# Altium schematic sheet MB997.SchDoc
size A4; DocumentNumber: 1; Revision: C.1(PCB.SCH); SheetNumber: 1; SheetTotal: 6; PageSetup: Record=PageOptions|CenterHorizontal=True|CenterVertical=True|PrintScale=1.00|XCorrection=1.00|YCorrection=1.00|PrintKind=1|BorderSize=5000000|LeftOffset=0|BottomOffset=0|Orientation=2|PaperLength=1000|PaperWidth=1000|Scale=100|PaperSource=15|PrintQuality=1200|MediaType=1|DitherType=10|PaperKind=A4|PrintScaleMode=1
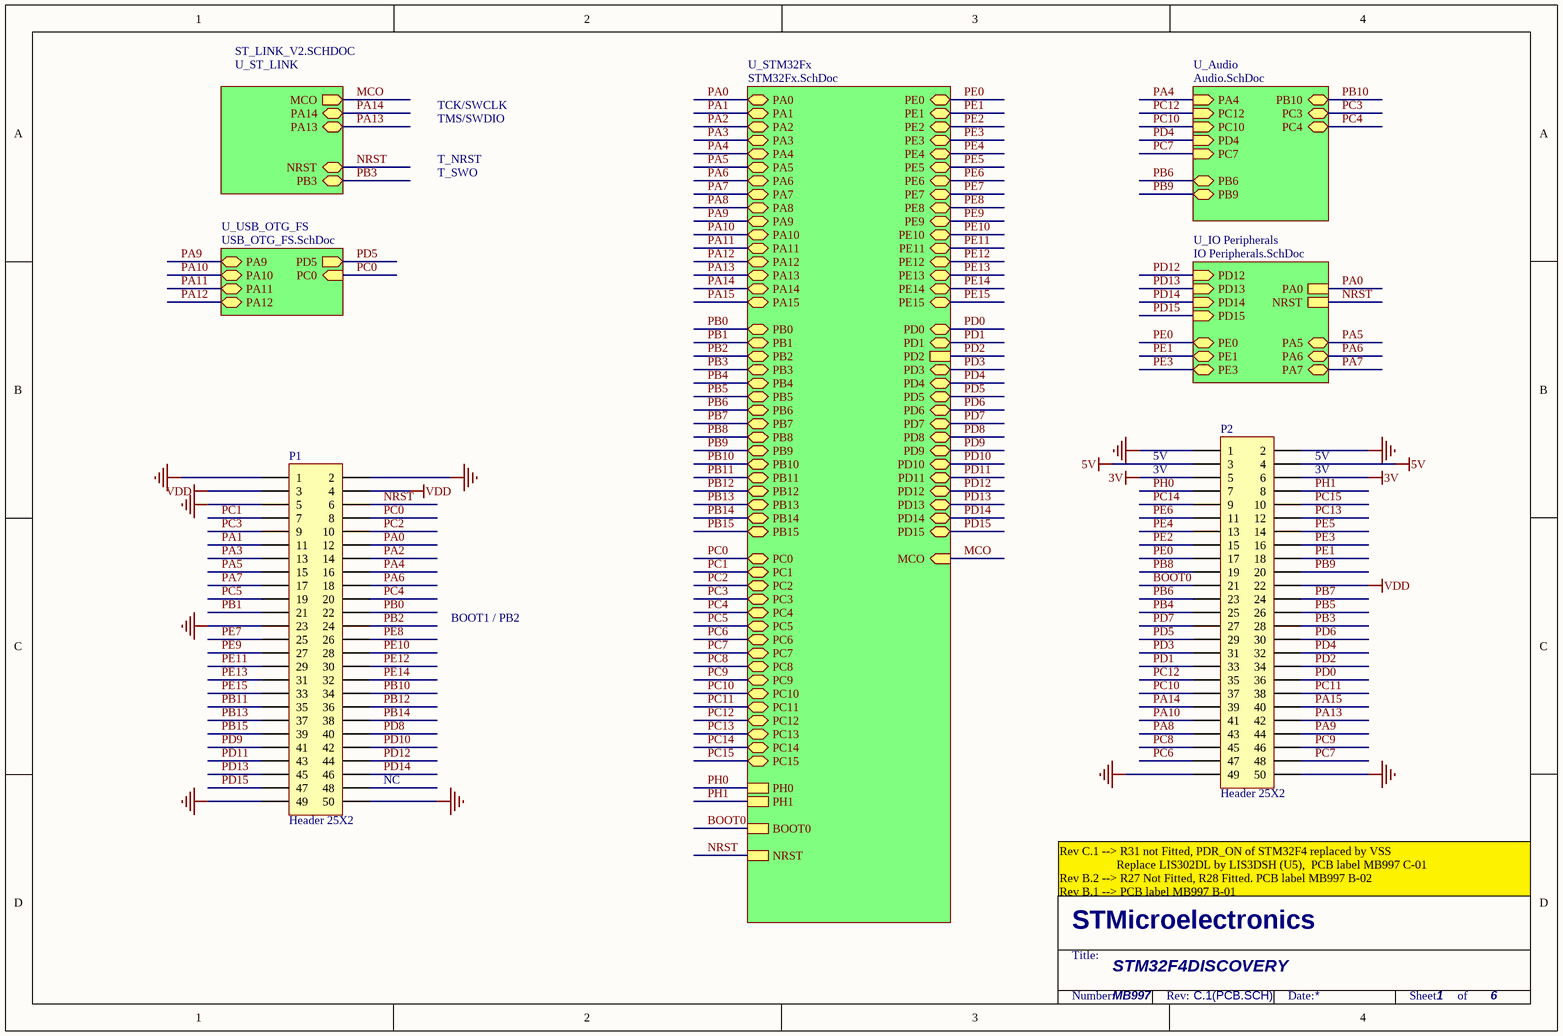
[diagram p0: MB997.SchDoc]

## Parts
P1  Header 25X2  [HDR2X25]
P2  Header 25X2  [HDR2X25]

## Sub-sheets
U_Audio = Audio.SchDoc: PA4 (in), PC12 (in), PC10 (in), PB6 (bidir), PB9 (bidir), PD4 (in), PC7 (in), PC3, PB10, PC4
U_IO Peripherals = IO Peripherals.SchDoc: PA0, NRST, PD12 (in), PE0, PD13 (in), PD14 (in), PD15 (in), PE1, PA5 (bidir), PA7 (bidir), PE3, PA6 (bidir)
U_ST_LINK = ST_LINK_V2.SCHDOC: PA13, PA14, NRST, PB3, MCO (out)
U_STM32Fx = STM32Fx.SchDoc: PA13 (bidir), PA14 (bidir), PA15 (bidir), PA12 (bidir), PA0 (bidir), PA1 (bidir), PA2 (bidir), PA3 (bidir), PA4 (bidir), PA5 (bidir), PA6 (bidir), PA7 (bidir), PA8 (bidir), PA9 (bidir), PA10 (bidir), PA11 (bidir), PB12 (bidir), PB0 (bidir), PB1 (bidir), PB2 (bidir), PB3 (bidir), PB4 (bidir), PB5 (bidir), PB6 (bidir), PB7 (bidir), PB8 (bidir), PB9 (bidir), PB10 (bidir), PB11 (bidir), PB13 (bidir), PB14 (bidir), PB15 (bidir), PC3 (bidir), PC15 (bidir), PC14 (bidir), PC13 (bidir), PC12 (bidir), PC11 (bidir), PC10 (bidir), PC9 (bidir), PC8 (bidir), PC7 (bidir), PC6 (bidir), PC5 (bidir), PC4 (bidir), PC2 (bidir), PC1 (bidir), PC0 (bidir), PD2, BOOT0, PH1, PH0, NRST, MCO (in), PE0, PE1, PE2, PE3, PE4, PE5, PE6, PE7, PE8, PE9, PE10, PE11, PE12, PE13, PE14, PE15, PD0, PD1, PD3, PD4, PD5, PD6, PD7, PD8, PD9, PD10, PD11, PD12, PD13, PD14, PD15
U_USB_OTG_FS = USB_OTG_FS.SchDoc: PD5 (out), PA11 (bidir), PA12 (bidir), PC0 (in), PA10 (bidir), PA9 (bidir)

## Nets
3V: P2.5 P2.6
5V: P2.3 P2.4
GND: P1.1 P1.2 P1.5 P1.23 P1.49 P1.50 P2.1 P2.2 P2.49 P2.50
VDD: P1.3 P1.4 P2.22
BOOT0: P2.21 ; sheet U_STM32Fx/BOOT0
MCO: sheet U_ST_LINK/MCO, sheet U_STM32Fx/MCO
NRST: P1.6 ; sheet U_ST_LINK/NRST, sheet U_IO Peripherals/NRST, sheet U_STM32Fx/NRST
PA0: P1.12 ; sheet U_IO Peripherals/PA0, sheet U_STM32Fx/PA0
PA1: P1.11 ; sheet U_STM32Fx/PA1
PA2: P1.14 ; sheet U_STM32Fx/PA2
PA3: P1.13 ; sheet U_STM32Fx/PA3
PA4: P1.16 ; sheet U_Audio/PA4, sheet U_STM32Fx/PA4
PA5: P1.15 ; sheet U_IO Peripherals/PA5, sheet U_STM32Fx/PA5
PA6: P1.18 ; sheet U_IO Peripherals/PA6, sheet U_STM32Fx/PA6
PA7: P1.17 ; sheet U_IO Peripherals/PA7, sheet U_STM32Fx/PA7
PA8: P2.43 ; sheet U_STM32Fx/PA8
PA9: P2.44 ; sheet U_STM32Fx/PA9, sheet U_USB_OTG_FS/PA9
PA10: P2.41 ; sheet U_STM32Fx/PA10, sheet U_USB_OTG_FS/PA10
PA11: sheet U_STM32Fx/PA11, sheet U_USB_OTG_FS/PA11
PA12: sheet U_STM32Fx/PA12, sheet U_USB_OTG_FS/PA12
PA13: P2.42 ; sheet U_ST_LINK/PA13, sheet U_STM32Fx/PA13
PA14: P2.39 ; sheet U_ST_LINK/PA14, sheet U_STM32Fx/PA14
PA15: P2.40 ; sheet U_STM32Fx/PA15
PB0: P1.22 ; sheet U_STM32Fx/PB0
PB1: P1.21 ; sheet U_STM32Fx/PB1
PB2: P1.24 ; sheet U_STM32Fx/PB2
PB3: P2.28 ; sheet U_ST_LINK/PB3, sheet U_STM32Fx/PB3
PB4: P2.25 ; sheet U_STM32Fx/PB4
PB5: P2.26 ; sheet U_STM32Fx/PB5
PB6: P2.23 ; sheet U_Audio/PB6, sheet U_STM32Fx/PB6
PB7: P2.24 ; sheet U_STM32Fx/PB7
PB8: P2.19 ; sheet U_STM32Fx/PB8
PB9: P2.20 ; sheet U_Audio/PB9, sheet U_STM32Fx/PB9
PB10: P1.34 ; sheet U_Audio/PB10, sheet U_STM32Fx/PB10
PB11: P1.35 ; sheet U_STM32Fx/PB11
PB12: P1.36 ; sheet U_STM32Fx/PB12
PB13: P1.37 ; sheet U_STM32Fx/PB13
PB14: P1.38 ; sheet U_STM32Fx/PB14
PB15: P1.39 ; sheet U_STM32Fx/PB15
PC0: P1.8 ; sheet U_STM32Fx/PC0, sheet U_USB_OTG_FS/PC0
PC1: P1.7 ; sheet U_STM32Fx/PC1
PC2: P1.10 ; sheet U_STM32Fx/PC2
PC3: P1.9 ; sheet U_Audio/PC3, sheet U_STM32Fx/PC3
PC4: P1.20 ; sheet U_Audio/PC4, sheet U_STM32Fx/PC4
PC5: P1.19 ; sheet U_STM32Fx/PC5
PC6: P2.47 ; sheet U_STM32Fx/PC6
PC7: P2.48 ; sheet U_Audio/PC7, sheet U_STM32Fx/PC7
PC8: P2.45 ; sheet U_STM32Fx/PC8
PC9: P2.46 ; sheet U_STM32Fx/PC9
PC10: P2.37 ; sheet U_Audio/PC10, sheet U_STM32Fx/PC10
PC11: P2.38 ; sheet U_STM32Fx/PC11
PC12: P2.35 ; sheet U_Audio/PC12, sheet U_STM32Fx/PC12
PC13: P2.12 ; sheet U_STM32Fx/PC13
PC14: P2.9 ; sheet U_STM32Fx/PC14
PC15: P2.10 ; sheet U_STM32Fx/PC15
PD0: P2.36 ; sheet U_STM32Fx/PD0
PD1: P2.33 ; sheet U_STM32Fx/PD1
PD2: P2.34 ; sheet U_STM32Fx/PD2
PD3: P2.31 ; sheet U_STM32Fx/PD3
PD4: P2.32 ; sheet U_Audio/PD4, sheet U_STM32Fx/PD4
PD5: P2.29 ; sheet U_STM32Fx/PD5, sheet U_USB_OTG_FS/PD5
PD6: P2.30 ; sheet U_STM32Fx/PD6
PD7: P2.27 ; sheet U_STM32Fx/PD7
PD8: P1.40 ; sheet U_STM32Fx/PD8
PD9: P1.41 ; sheet U_STM32Fx/PD9
PD10: P1.42 ; sheet U_STM32Fx/PD10
PD11: P1.43 ; sheet U_STM32Fx/PD11
PD12: P1.44 ; sheet U_IO Peripherals/PD12, sheet U_STM32Fx/PD12
PD13: P1.45 ; sheet U_IO Peripherals/PD13, sheet U_STM32Fx/PD13
PD14: P1.46 ; sheet U_IO Peripherals/PD14, sheet U_STM32Fx/PD14
PD15: P1.47 ; sheet U_IO Peripherals/PD15, sheet U_STM32Fx/PD15
PE0: P2.17 ; sheet U_IO Peripherals/PE0, sheet U_STM32Fx/PE0
PE1: P2.18 ; sheet U_IO Peripherals/PE1, sheet U_STM32Fx/PE1
PE2: P2.15 ; sheet U_STM32Fx/PE2
PE3: P2.16 ; sheet U_IO Peripherals/PE3, sheet U_STM32Fx/PE3
PE4: P2.13 ; sheet U_STM32Fx/PE4
PE5: P2.14 ; sheet U_STM32Fx/PE5
PE6: P2.11 ; sheet U_STM32Fx/PE6
PE7: P1.25 ; sheet U_STM32Fx/PE7
PE8: P1.26 ; sheet U_STM32Fx/PE8
PE9: P1.27 ; sheet U_STM32Fx/PE9
PE10: P1.28 ; sheet U_STM32Fx/PE10
PE11: P1.29 ; sheet U_STM32Fx/PE11
PE12: P1.30 ; sheet U_STM32Fx/PE12
PE13: P1.31 ; sheet U_STM32Fx/PE13
PE14: P1.32 ; sheet U_STM32Fx/PE14
PE15: P1.33 ; sheet U_STM32Fx/PE15
PH0: P2.7 ; sheet U_STM32Fx/PH0
PH1: P2.8 ; sheet U_STM32Fx/PH1

Not connected (* = marked no-connect by the designer): P1 48

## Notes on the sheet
- TCK/SWCLK
- TMS/SWDIO
- T_SWO
- T_NRST
- 5V
- 3V
- (near P2) 5V
- (near P2) 3V
- BOOT1 / PB2
- (near P1) NC
- Rev C.1 --> R31 not Fitted, PDR_ON of STM32F4 replaced by VSS
  Replace LIS302DL by LIS3DSH (U5),  PCB label MB997 C-01
  Rev B.2 --> R27 Not Fitted, R28 Fitted. PCB label MB997 B-02
  Rev B.1 --> PCB label MB997 B-01
- STM32F4DISCOVERY
- MB997
- 1

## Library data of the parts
P1 P2 = Header 25X2: Header, 25-Pin, Dual row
